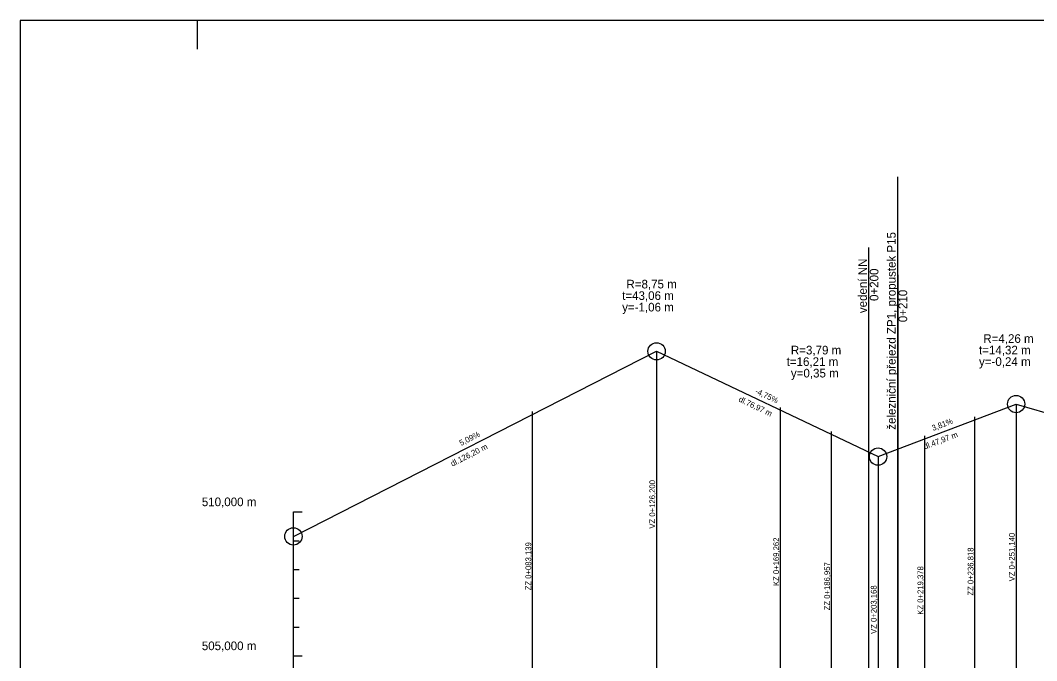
# Model space of a CAD drawing. Extents: x -632716 to -629545, y -1094726 to -1088285.
# Drawn here: x -632546.8 to -632193.7, y -1090007.3 to -1089784.9 of the extents above; entities that cross this region are included whole.
import ezdxf

# ---------------------------------------------------------------- set-up
doc = ezdxf.new("R2010")
doc.units = 0
for name, color, linetype in [('formát', 7, 'Continuous'), ('REZ_POPIS', 7, 'Continuous'), ('REZ_TENKA', 7, 'Continuous'), ('REZ_TLUSTA', 7, 'Continuous'), ('SKLONY_NIVELETA', 7, 'Continuous'), ('SKLONY_POPIS', 7, 'Continuous'), ('TECNY_NIVELETA', 7, 'Continuous')]:
    doc.layers.add(name, color=color, linetype=linetype)

msp = doc.modelspace()

# ---------------------------------------------------------------- linework, layer by layer
at = {"layer": 'formát'}
msp.add_line((-632485.24, -1089794.9), (-632485.24, -1089784.9), dxfattribs=at)
msp.add_lwpolyline([(-632546.83, -1090378.9), (-629545.24, -1090378.9), (-629545.24, -1089784.9), (-632546.83, -1089784.9)], close=True, dxfattribs=at)
at = {"layer": 'REZ_TENKA'}
for p, q in [((-632451.95, -1090255.62), (-632451.95, -1089955.62)), ((-632451.95, -1089965.62), (-632449.95, -1089965.62)), ((-632451.95, -1089975.62), (-632449.95, -1089975.62)), ((-632451.95, -1089985.62), (-632449.95, -1089985.62)), ((-632451.95, -1089995.62), (-632449.95, -1089995.62))]:
    msp.add_line(p, q, dxfattribs=at)
at = {"layer": 'REZ_TLUSTA'}
for p, q in [((-632451.95, -1089955.62), (-632448.95, -1089955.62)), ((-632451.95, -1089955.62), (-632448.95, -1089955.62)), ((-632451.95, -1090005.62), (-632448.95, -1090005.62))]:
    msp.add_line(p, q, dxfattribs=at)
at = {"layer": 'SKLONY_NIVELETA'}
for p, q in [((-632241.95, -1089873.26), (-632241.95, -1090032.65)), ((-632451.95, -1089964.11), (-632325.75, -1089899.84)), ((-632325.75, -1089899.84), (-632325.75, -1090255.62)), ((-632325.75, -1089899.84), (-632248.79, -1089936.41)), ((-632248.79, -1089936.41), (-632200.81, -1089918.16)), ((-632200.81, -1089918.16), (-632200.81, -1090255.62)), ((-632200.81, -1089918.16), (-631995.31, -1089978.26)), ((-632248.79, -1089936.41), (-632248.79, -1090255.62)), ((-632451.95, -1089964.11), (-632451.95, -1089964.11))]:
    msp.add_line(p, q, dxfattribs=at)
for centre in [(-632325.75, -1089899.84), (-632200.81, -1089918.16), (-632248.79, -1089936.41), (-632451.95, -1089964.11)]:
    msp.add_circle(centre, 3, dxfattribs=at)
at = {"layer": 'TECNY_NIVELETA'}
for p, q in [((-632241.95, -1090032.65), (-632241.95, -1089839.22)), ((-632251.95, -1090032.66), (-632251.95, -1089863.77)), ((-632325.75, -1089899.84), (-632325.75, -1089899.84)), ((-632282.69, -1090020.3), (-632282.69, -1089919.3)), ((-632200.81, -1089918.16), (-632200.81, -1089918.16)), ((-632368.81, -1090021.77), (-632368.81, -1089920.77)), ((-632215.14, -1090023.61), (-632215.14, -1089922.61)), ((-632265, -1090028.71), (-632265, -1089927.71)), ((-632232.58, -1090030.24), (-632232.58, -1089929.24)), ((-632248.79, -1089936.41), (-632248.79, -1089936.41)), ((-632451.95, -1089964.11), (-632451.95, -1089964.11))]:
    msp.add_line(p, q, dxfattribs=at)

# ---------------------------------------------------------------- texts
at = {"layer": 'REZ_POPIS'}
for s, p in [('510,000 m', (-632483.77, -1089953.62)), ('510,000 m', (-632483.77, -1089953.62)), ('505,000 m', (-632483.77, -1090003.62))]:
    msp.add_text(s, height=3, dxfattribs=at).set_placement(p)
at = {"layer": 'SKLONY_POPIS'}
for s, height, rotation, p in [('železniční přejezd ZP1, propustek P15', 3, 90, (-632242.67, -1089927.09)), ('vedení NN', 3, 90, (-632252.67, -1089886.58)), ('0+200', 3, 90, (-632248.67, -1089882.36)), ('0+210', 3, 90, (-632238.67, -1089889.73)), ('-4,75%', 2, 334.5823, (-632291.71, -1089914.35)), ('dl.76,97 m', 2, 334.5823, (-632297.44, -1089917.17)), ('3,81%', 2, 20.8338, (-632229.67, -1089927.53)), ('5,09%', 2, 26.9892, (-632393.67, -1089932.74)), ('dl.47,97 m', 2, 20.8338, (-632232.53, -1089933.97)), ('dl.126,20 m', 2, 26.9892, (-632396.7, -1089939.9)), ('VZ 0+126,200', 2, 90, (-632326.25, -1089961.42)), ('ZZ 0+083,139', 2, 90, (-632369.31, -1089982.85)), ('KZ 0+169,262', 2, 90, (-632283.19, -1089981.38)), ('VZ 0+251,140', 2, 90, (-632201.31, -1089979.74)), ('ZZ 0+236,818', 2, 90, (-632215.64, -1089984.69)), ('ZZ 0+186,957', 2, 90, (-632265.5, -1089989.79)), ('KZ 0+219,378', 2, 90, (-632233.08, -1089991.33)), ('VZ 0+203,168', 2, 90, (-632249.29, -1089998))]:
    msp.add_text(s, height=height, rotation=rotation, dxfattribs=at).set_placement(p)
for s, p in [('R=8,75 m', (-632336.22, -1089878)), ('t=43,06 m', (-632337.71, -1089882)), ('y=-1,06 m', (-632337.71, -1089886)), ('R=4,26 m', (-632212.23, -1089896.91)), ('R=3,79 m', (-632279.08, -1089900.92)), ('t=14,32 m', (-632213.72, -1089900.91)), ('t=16,21 m', (-632280.56, -1089904.92)), ('y=-0,24 m', (-632213.72, -1089904.91)), ('y=0,35 m', (-632279.08, -1089908.92))]:
    msp.add_text(s, height=3, dxfattribs=at).set_placement(p)

doc.saveas('drawing.dxf')
